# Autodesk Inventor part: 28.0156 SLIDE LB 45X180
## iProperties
Created: 2007-06
Part Number: 28.0156 SLIDE LB 45X180
Material: Aluminum-6061
Document SubType Name: Modeling
Designer: Andy Moles
Density: 1 g/cm^3
Author: Andy Moles
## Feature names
1. Extrusion1
2. Extrusion2
3. Mirror1
